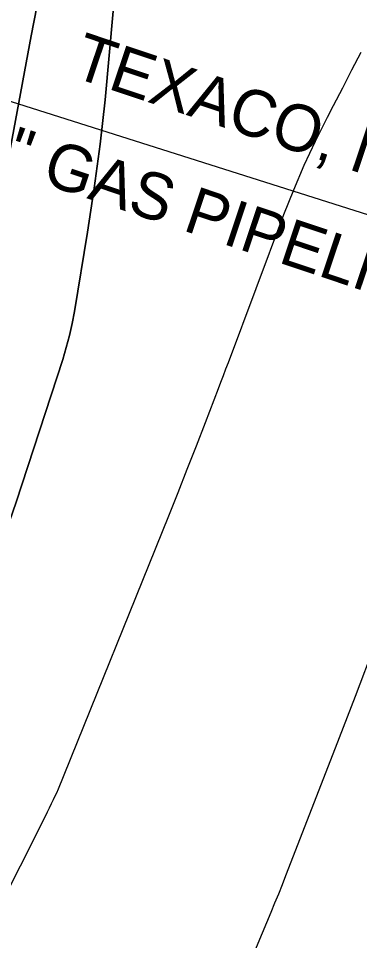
# Model space of a CAD drawing. Extents: x 3925854 to 3964121, y 224593 to 250589.
# Drawn here: x 3941160 to 3941766, y 231140 to 232780 of the extents above; entities that cross this region are included whole.
import ezdxf

# ---------------------------------------------------------------- set-up
doc = ezdxf.new("R2010")
doc.units = 0
for name, color, linetype in [('V-TOPO-DPTH', 7, 'Continuous'), ('V-TOPO-MAJR', 7, 'Continuous'), ('V-TOPO-MINR', 7, 'Continuous'), ('V-UTIL-IDEN', 7, 'Continuous'), ('V-UTIL-LINE', 7, 'Continuous')]:
    doc.layers.add(name, color=color, linetype=linetype)

msp = doc.modelspace()

# ---------------------------------------------------------------- linework, layer by layer
at = {"layer": 'V-TOPO-DPTH'}
for points in [[(3941197.73, 232828.069), (3941182.541, 232749.068), (3941089.043, 232249.474), (3941088.463, 232246.844), (3941087.715, 232244.258), (3941086.484, 232240.404), (3941086.08, 232239.118), (3941042.756, 232100.204), (3941020.439, 232029.543), (3940997.785, 231958.991), (3940974.625, 231888.603), (3940951.128, 231818.325), (3940831.453, 231527.83), (3940778.585, 231417.807), (3940749.942, 231356.296), (3940722.307, 231294.349), (3940696.185, 231231.75), (3940671.071, 231168.715), (3940471.587, 230649.777), (3940468.564, 230644.623), (3940464.787, 230640.393), (3940233.897, 230211.72)], [(3941076.606, 232208.74), (3941086.08, 232239.118), (3941086.484, 232240.404), (3941087.715, 232244.258), (3941088.463, 232246.844), (3941089.043, 232249.474), (3941182.541, 232749.068), (3941197.73, 232828.069)], [(3941328.026, 232792.565), (3941320.894, 232713.763), (3941313.617, 232634.984), (3941305.01, 232556.367), (3941294.409, 232477.995), (3941282.479, 232399.785), (3941259.151, 232258.889), (3941255.067, 232237.266), (3941250.342, 232215.8), (3941244.654, 232194.568), (3941238.325, 232173.493), (3941155.908, 231919.991), (3941131.793, 231851.23), (3941105.618, 231783.318), (3940932.968, 231517.244), (3940575.717, 230618.667), (3940572.491, 230613.088), (3940568.362, 230608.854), (3940376.027, 230214.305)], [(3941726.951, 230238.869), (3940376.027, 230214.305), (3940568.362, 230608.854), (3940572.491, 230613.088), (3940575.717, 230618.667), (3940932.968, 231517.244), (3941105.618, 231783.318), (3941131.793, 231851.23), (3941155.908, 231919.991), (3941238.325, 232173.493), (3941244.654, 232194.568), (3941250.342, 232215.8), (3941255.067, 232237.266), (3941259.151, 232258.889), (3941282.479, 232399.785), (3941294.409, 232477.995), (3941305.01, 232556.367), (3941313.617, 232634.984), (3941320.894, 232713.763), (3941328.026, 232792.565)]]:
    msp.add_lwpolyline(points, dxfattribs=at)
at = {"layer": 'V-TOPO-MAJR'}
for points in [[(3941768.333, 232719.2), (3941752.125, 232687.572), (3941735.818, 232655.996), (3941719.444, 232624.453), (3941708.476, 232603.404), (3941687.352, 232561.013), (3941667.27, 232518.156), (3941648.749, 232474.602), (3941631.269, 232430.583), (3941532.361, 232167.74), (3941527.96, 232156.077), (3941523.546, 232144.419), (3941519.112, 232132.77), (3941514.663, 232121.125), (3941491.621, 232060.969), (3941475.529, 232019.294), (3941459.288, 231977.678), (3941442.822, 231936.15), (3941426.206, 231894.682), (3941229.131, 231406.64), (3941228.603, 231405.389), (3941228.322, 231404.771), (3941228.034, 231404.157), (3941221.48, 231390.537), (3941217.888, 231383.125), (3941214.27, 231375.727), (3941210.613, 231368.347), (3941206.929, 231360.981), (3940805.398, 230563.5)], [(3941217.511, 230229.605), (3941224.408, 230254.117), (3941232.362, 230280.543), (3941240.942, 230306.751), (3941250.462, 230332.633), (3941260.61, 230358.296), (3941315.751, 230490.711), (3941353.979, 230582.402), (3941392.259, 230674.071), (3941430.617, 230765.708), (3941469.027, 230857.323), (3941609.061, 231190.932), (3941615.792, 231207.152), (3941622.436, 231223.407), (3941628.948, 231239.716), (3941635.371, 231256.06), (3941723.425, 231482.782), (3941758.93, 231574.965), (3941794.092, 231667.278)]]:
    msp.add_lwpolyline(points, dxfattribs=at)
at = {"layer": 'V-TOPO-MINR'}
for points in [[(3941197.73, 232828.069), (3941182.541, 232749.068), (3941089.043, 232249.474), (3941088.463, 232246.844), (3941087.715, 232244.258), (3941086.484, 232240.404), (3941086.08, 232239.118), (3941042.756, 232100.204), (3941020.439, 232029.543), (3940997.785, 231958.991), (3940974.625, 231888.603), (3940951.128, 231818.325), (3940831.453, 231527.83), (3940778.585, 231417.807), (3940749.942, 231356.296), (3940722.307, 231294.349), (3940696.185, 231231.75), (3940671.071, 231168.715), (3940471.587, 230649.777), (3940468.564, 230644.623), (3940464.787, 230640.393), (3940233.897, 230211.72)], [(3941328.026, 232792.565), (3941320.894, 232713.763), (3941313.617, 232634.984), (3941305.01, 232556.367), (3941294.409, 232477.995), (3941282.479, 232399.785), (3941259.151, 232258.889), (3941255.067, 232237.266), (3941250.342, 232215.8), (3941244.654, 232194.568), (3941238.325, 232173.493), (3941155.908, 231919.991), (3941131.793, 231851.23), (3941105.618, 231783.318), (3940932.968, 231517.244), (3940575.717, 230618.667), (3940572.491, 230613.088), (3940568.362, 230608.854), (3940376.027, 230214.305)]]:
    msp.add_lwpolyline(points, dxfattribs=at)
at = {"layer": 'V-UTIL-LINE'}
msp.add_lwpolyline([(3944448.956, 231161.167), (3944066.619, 231705.838), (3939716.974, 233085.703), (3938914.857, 233883.421)], dxfattribs=at)

# ---------------------------------------------------------------- texts
at = {"layer": 'V-UTIL-IDEN'}
for s, p in [('TEXACO, INC.', (3941252.086, 232677.076)), ('1-8" GAS PIPELINE', (3940979.542, 232561.059))]:
    msp.add_text(s, height=82.99983, rotation=341.481312, dxfattribs=at).set_placement(p)

doc.saveas('drawing.dxf')
